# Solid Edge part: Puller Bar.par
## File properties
Author: Dan
Template: metric part.par
Last saved by: Dan
Revision: 8
Application: Solid Edge
Density: 7833.000 kg/m^3
Accuracy: 0.990
Material: Steel
Face Style: Steel
Fill Style: ANSI32(Steel)
Virtual Style: Machined steel
Coef. of Thermal Exp: 1.3e-05
Thermal Conductivity: 32.0
Specific Heat: 481.0
Modulus of Elasticity: 199947953000.0
Poisson's Ratio: 0.29
Yield Stress: 262000766.0
Ultimate Stress: 358527364.0
Elongation: 0.0
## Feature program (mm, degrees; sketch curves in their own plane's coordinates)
sketch for "unnamed Protrusion 1" plane through (0, 0, 0) normal (0, 0, 1) x-axis (1, 0, 0)
extrude "unnamed Protrusion 1" add finite 19.7 along -normal
sketch for "unnamed Cutout 1" plane through (0, 0, 0) normal (0, 0, 1) x-axis (1, 0, 0)
extrude "unnamed Cutout 1" cut through along -normal
fillet "Round_1" radius 6
fillet "Round_2" radius 6
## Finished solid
Body 1: solid body, 18 faces, 48 edges, 32 vertices.
  Faces by surface: plane 10, cylinder 8
  Edges by curve: line 32, circle 16
Bounding box of the edges (mm): 250.000 x 30.000 x 19.700, from (-125, -15, -19.7) to (125, 15, 0).
Cylindrical faces by radius (mm): R6 x8
Planar faces by outward normal: +x 2, +y 2, +z 1, -x 2, -y 2, -z 1
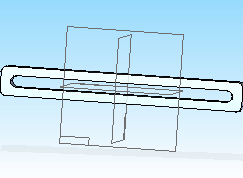
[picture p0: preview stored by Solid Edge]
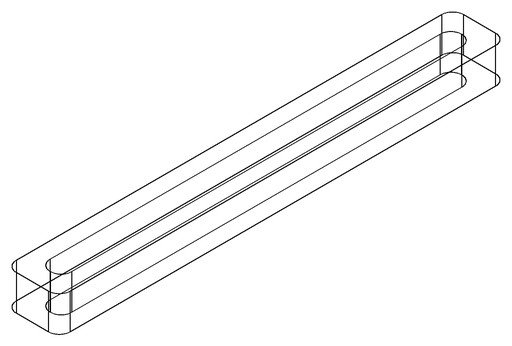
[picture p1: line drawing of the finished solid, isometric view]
